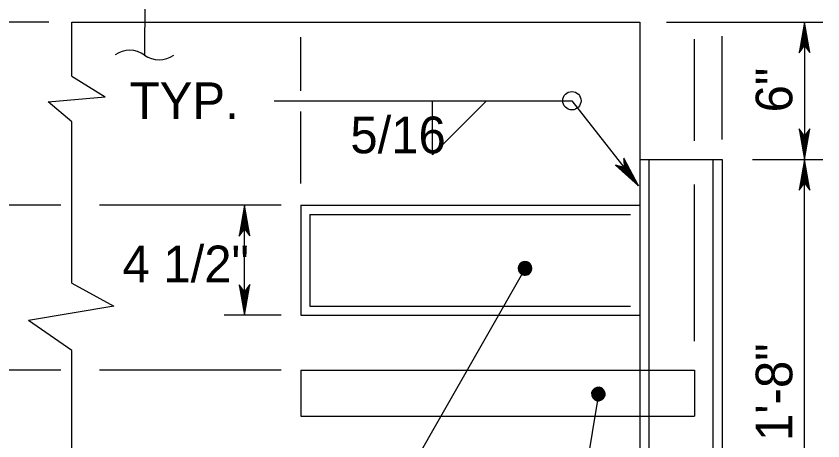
# Model space of a CAD drawing. Extents: x 499866 to 500993, y 499985 to 500645.
# Drawn here: x 500302.2 to 500390.2, y 500532.5 to 500578.8 of the extents above; entities that cross this region are included whole.
import ezdxf

# ---------------------------------------------------------------- set-up
doc = ezdxf.new("R2010")
doc.units = 0
doc.layers.add('24', color=7, linetype='Continuous')
doc.layers.add('5', color=7, linetype='Continuous')

msp = doc.modelspace()

# ---------------------------------------------------------------- linework, layer by layer
at = {"layer": '24'}
for points in [[(500388.193, 500578.176), (500387.6, 500574.826), (500388.193, 500575.626), (500388.776, 500574.843), (500388.193, 500578.176), (500388.198, 500577.953), (500387.644, 500574.92), (500388.2, 500575.689), (500388.73, 500574.978), (500388.209, 500577.833), (500388.193, 500577.722), (500387.731, 500575.123), (500388.199, 500575.706), (500388.654, 500575.107), (500388.192, 500577.671), (500388.209, 500577.559), (500387.799, 500575.288), (500388.192, 500575.73), (500388.601, 500575.279), (500388.21, 500577.236), (500388.209, 500577.047), (500387.884, 500575.456), (500388.183, 500575.766), (500388.516, 500575.432), (500388.193, 500577.013), (500388.182, 500576.834), (500387.977, 500575.638), (500388.21, 500575.868), (500388.439, 500575.619), (500388.193, 500576.67), (500388.176, 500576.501), (500388.038, 500575.783), (500388.2, 500575.901), (500388.379, 500575.706), (500388.192, 500576.414), (500388.081, 500575.945), (500388.209, 500576.013), (500388.338, 500575.807), (500388.21, 500576.296), (500388.133, 500575.989), (500388.234, 500576.117), (500388.294, 500575.969), (500388.2, 500576.116), (500388.183, 500576.04)], [(500388.193, 500563.187), (500388.785, 500566.537), (500388.193, 500565.737), (500387.61, 500566.52), (500388.193, 500563.187), (500388.187, 500563.409), (500388.741, 500566.443), (500388.185, 500565.674), (500387.656, 500566.385), (500388.176, 500563.53), (500388.193, 500563.641), (500388.655, 500566.24), (500388.186, 500565.657), (500387.731, 500566.256), (500388.193, 500563.692), (500388.176, 500563.803), (500388.586, 500566.075), (500388.193, 500565.633), (500387.784, 500566.084), (500388.176, 500564.127), (500388.176, 500564.316), (500388.502, 500565.906), (500388.202, 500565.597), (500387.869, 500565.93), (500388.193, 500564.35), (500388.203, 500564.529), (500388.408, 500565.724), (500388.176, 500565.494), (500387.947, 500565.744), (500388.193, 500564.693), (500388.21, 500564.862), (500388.347, 500565.58), (500388.185, 500565.462), (500388.007, 500565.657), (500388.193, 500564.949), (500388.304, 500565.418), (500388.176, 500565.35), (500388.048, 500565.555), (500388.176, 500565.067), (500388.253, 500565.374), (500388.152, 500565.245), (500388.091, 500565.393), (500388.185, 500565.246), (500388.202, 500565.323)], [(500370.066, 500560.316), (500368.469, 500563.32), (500368.496, 500562.324), (500367.554, 500562.582), (500370.066, 500560.316), (500369.925, 500560.488), (500368.492, 500563.219), (500368.528, 500562.271), (500367.673, 500562.504), (500369.842, 500560.576), (500369.786, 500560.674), (500368.55, 500563.005), (500368.539, 500562.257), (500367.812, 500562.449), (500369.755, 500560.714), (500369.674, 500560.791), (500368.597, 500562.833), (500368.56, 500562.243), (500367.96, 500562.346), (500369.474, 500561.046), (500369.358, 500561.195), (500368.635, 500562.649), (500368.589, 500562.22), (500368.121, 500562.278), (500369.35, 500561.232), (500369.248, 500561.379), (500368.673, 500562.447), (500368.631, 500562.123), (500368.297, 500562.178), (500369.138, 500561.502), (500369.048, 500561.645), (500368.714, 500562.296), (500368.659, 500562.103), (500368.398, 500562.147), (500368.981, 500561.704), (500368.78, 500562.142), (500368.721, 500562.01), (500368.493, 500562.092), (500368.895, 500561.786), (500368.766, 500562.076), (500368.766, 500561.912), (500368.627, 500561.991), (500368.792, 500561.934), (500368.758, 500562.005)], [(500388.193, 500563.187), (500387.6, 500559.837), (500388.193, 500560.637), (500388.776, 500559.854), (500388.193, 500563.187), (500388.198, 500562.965), (500387.644, 500559.931), (500388.2, 500560.7), (500388.73, 500559.99), (500388.209, 500562.844), (500388.193, 500562.733), (500387.731, 500560.134), (500388.199, 500560.717), (500388.654, 500560.118), (500388.192, 500562.682), (500388.209, 500562.571), (500387.799, 500560.299), (500388.192, 500560.741), (500388.601, 500560.29), (500388.21, 500562.247), (500388.209, 500562.058), (500387.884, 500560.468), (500388.183, 500560.777), (500388.516, 500560.444), (500388.193, 500562.024), (500388.182, 500561.845), (500387.977, 500560.65), (500388.21, 500560.88), (500388.439, 500560.63), (500388.193, 500561.681), (500388.176, 500561.512), (500388.038, 500560.794), (500388.2, 500560.912), (500388.379, 500560.717), (500388.192, 500561.425), (500388.081, 500560.956), (500388.209, 500561.024), (500388.338, 500560.819), (500388.21, 500561.307), (500388.133, 500561), (500388.234, 500561.129), (500388.294, 500560.981), (500388.2, 500561.128), (500388.183, 500561.051)], [(500327.091, 500558.191), (500326.499, 500554.841), (500327.091, 500555.641), (500327.674, 500554.858), (500327.091, 500558.191), (500327.097, 500557.969), (500326.543, 500554.935), (500327.098, 500555.704), (500327.628, 500554.993), (500327.108, 500557.848), (500327.091, 500557.737), (500326.629, 500555.138), (500327.098, 500555.721), (500327.553, 500555.122), (500327.091, 500557.686), (500327.108, 500557.574), (500326.698, 500555.303), (500327.091, 500555.745), (500327.5, 500555.294), (500327.108, 500557.251), (500327.108, 500557.062), (500326.782, 500555.471), (500327.082, 500555.781), (500327.415, 500555.448), (500327.091, 500557.028), (500327.081, 500556.849), (500326.876, 500555.654), (500327.108, 500555.884), (500327.337, 500555.634), (500327.091, 500556.685), (500327.074, 500556.516), (500326.937, 500555.798), (500327.098, 500555.916), (500327.277, 500555.721), (500327.091, 500556.429), (500326.98, 500555.96), (500327.108, 500556.028), (500327.236, 500555.823), (500327.108, 500556.311), (500327.031, 500556.004), (500327.132, 500556.133), (500327.193, 500555.985), (500327.098, 500556.132), (500327.082, 500556.055)], [(500357.7, 500551.309), (500315.017, 500476.505), (500305.426, 500476.505)], [(500327.091, 500546.2), (500327.683, 500549.55), (500327.091, 500548.75), (500326.508, 500549.533), (500327.091, 500546.2), (500327.085, 500546.423), (500327.639, 500549.456), (500327.084, 500548.687), (500326.554, 500549.398), (500327.075, 500546.543), (500327.091, 500546.654), (500327.553, 500549.253), (500327.084, 500548.67), (500326.63, 500549.269), (500327.092, 500546.705), (500327.075, 500546.817), (500327.485, 500549.088), (500327.092, 500548.646), (500326.683, 500549.097), (500327.074, 500547.14), (500327.075, 500547.329), (500327.4, 500548.92), (500327.101, 500548.61), (500326.768, 500548.944), (500327.091, 500547.363), (500327.102, 500547.542), (500327.306, 500548.738), (500327.074, 500548.508), (500326.845, 500548.757), (500327.091, 500547.706), (500327.108, 500547.875), (500327.245, 500548.593), (500327.084, 500548.475), (500326.905, 500548.67), (500327.092, 500547.962), (500327.203, 500548.431), (500327.075, 500548.363), (500326.946, 500548.569), (500327.074, 500548.08), (500327.151, 500548.387), (500327.05, 500548.259), (500326.99, 500548.406), (500327.084, 500548.26), (500327.101, 500548.336)], [(500365.696, 500537.609), (500358.156, 500491.828), (500352.28, 500491.828)]]:
    msp.add_lwpolyline(points, dxfattribs=at)
for centre, radius, start, end in [((500314.573, 500572.326), 2.768, 54.46959, 124.83479), ((500317.791, 500576.831), 2.768, 234.46959, 304.83479), ((500357.7, 500551.309), 0.738, 60.29128, 240.29128), ((500357.7, 500551.309), 0.714, 60.29128, 240.29128), ((500357.7, 500551.309), 0.689, 60.29128, 240.29128), ((500357.7, 500551.309), 0.664, 60.29128, 240.29128), ((500357.7, 500551.309), 0.64, 60.29128, 240.29128), ((500357.7, 500551.309), 0.615, 60.29128, 240.29128), ((500357.7, 500551.309), 0.591, 60.29128, 240.29128), ((500357.7, 500551.309), 0.566, 60.29128, 240.29128), ((500357.7, 500551.309), 0.541, 60.29128, 240.29128), ((500357.7, 500551.309), 0.517, 60.29128, 240.29128), ((500357.7, 500551.309), 0.492, 60.29128, 240.29128), ((500357.7, 500551.309), 0.468, 60.29128, 240.29128), ((500357.7, 500551.309), 0.443, 60.29128, 240.29128), ((500357.7, 500551.309), 0.418, 60.29128, 240.29128), ((500357.7, 500551.309), 0.394, 60.29128, 240.29128), ((500357.7, 500551.309), 0.369, 60.29128, 240.29128), ((500357.7, 500551.309), 0.738, 240.29128, 60.29128), ((500357.7, 500551.309), 0.714, 240.29128, 60.29128), ((500357.7, 500551.309), 0.344, 60.29128, 240.29128), ((500357.7, 500551.309), 0.689, 240.29128, 60.29128), ((500357.7, 500551.309), 0.664, 240.29128, 60.29128), ((500357.7, 500551.309), 0.32, 60.29128, 240.29128), ((500357.7, 500551.309), 0.64, 240.29128, 60.29128), ((500357.7, 500551.309), 0.615, 240.29128, 60.29128), ((500357.7, 500551.309), 0.295, 60.29128, 240.29128), ((500357.7, 500551.309), 0.591, 240.29128, 60.29128), ((500357.7, 500551.309), 0.566, 240.29128, 60.29128), ((500357.7, 500551.309), 0.271, 60.29128, 240.29128), ((500357.7, 500551.309), 0.541, 240.29128, 60.29128), ((500357.7, 500551.309), 0.517, 240.29128, 60.29128), ((500357.7, 500551.309), 0.246, 60.29128, 240.29128), ((500357.7, 500551.309), 0.492, 240.29128, 60.29128), ((500357.7, 500551.309), 0.468, 240.29128, 60.29128), ((500357.7, 500551.309), 0.221, 60.29128, 240.29128), ((500357.7, 500551.309), 0.443, 240.29128, 60.29128), ((500357.7, 500551.309), 0.418, 240.29128, 60.29128), ((500357.7, 500551.309), 0.197, 60.29128, 240.29128), ((500357.7, 500551.309), 0.394, 240.29128, 60.29128), ((500357.7, 500551.309), 0.369, 240.29128, 60.29128), ((500357.7, 500551.309), 0.172, 60.29128, 240.29128), ((500357.7, 500551.309), 0.344, 240.29128, 60.29128), ((500357.7, 500551.309), 0.32, 240.29128, 60.29128), ((500357.7, 500551.309), 0.148, 60.29128, 240.29128), ((500357.7, 500551.309), 0.295, 240.29128, 60.29128), ((500357.7, 500551.309), 0.271, 240.29128, 60.29128), ((500357.7, 500551.309), 0.123, 60.29128, 240.29128), ((500357.7, 500551.309), 0.246, 240.29128, 60.29128), ((500357.7, 500551.309), 0.221, 240.29128, 60.29128), ((500357.7, 500551.309), 0.0984, 60.29128, 240.29128), ((500357.7, 500551.309), 0.197, 240.29128, 60.29128), ((500357.7, 500551.309), 0.172, 240.29128, 60.29128), ((500357.7, 500551.309), 0.0738, 60.29128, 240.29128), ((500357.7, 500551.309), 0.148, 240.29128, 60.29128), ((500357.7, 500551.309), 0.123, 240.29128, 60.29128), ((500357.7, 500551.309), 0.0984, 240.29128, 60.29128), ((500357.7, 500551.309), 0.0492, 60.29128, 240.29128), ((500357.7, 500551.309), 0.0738, 240.29128, 60.29128), ((500357.7, 500551.309), 0.0492, 240.29128, 60.29128), ((500357.7, 500551.309), 0.0246, 60.29128, 240.29128), ((500357.7, 500551.309), 0.0246, 240.29128, 60.29128), ((500365.695, 500537.609), 0.738, 80.64766, 260.64766), ((500365.695, 500537.609), 0.714, 80.64766, 260.64766), ((500365.695, 500537.609), 0.689, 80.64766, 260.64766), ((500365.695, 500537.609), 0.664, 80.64766, 260.64766), ((500365.695, 500537.609), 0.64, 80.64766, 260.64766), ((500365.695, 500537.609), 0.615, 80.64766, 260.64766), ((500365.695, 500537.609), 0.591, 80.64766, 260.64766), ((500365.695, 500537.609), 0.566, 80.64766, 260.64766), ((500365.695, 500537.609), 0.541, 80.64766, 260.64766), ((500365.695, 500537.609), 0.517, 80.64766, 260.64766), ((500365.695, 500537.609), 0.492, 80.64766, 260.64766), ((500365.695, 500537.609), 0.468, 80.64766, 260.64766), ((500365.695, 500537.609), 0.443, 80.64766, 260.64766), ((500365.695, 500537.609), 0.418, 80.64766, 260.64766), ((500365.695, 500537.609), 0.394, 80.64766, 260.64766), ((500365.695, 500537.609), 0.369, 80.64766, 260.64766), ((500365.695, 500537.609), 0.344, 80.64766, 260.64766), ((500365.695, 500537.609), 0.32, 80.64766, 260.64766), ((500365.695, 500537.609), 0.295, 80.64766, 260.64766), ((500365.695, 500537.609), 0.271, 80.64766, 260.64766), ((500365.695, 500537.609), 0.738, 260.64766, 80.64766), ((500365.695, 500537.609), 0.714, 260.64766, 80.64766), ((500365.695, 500537.609), 0.689, 260.64766, 80.64766), ((500365.695, 500537.609), 0.664, 260.64766, 80.64766), ((500365.695, 500537.609), 0.64, 260.64766, 80.64766), ((500365.695, 500537.609), 0.615, 260.64766, 80.64766), ((500365.695, 500537.609), 0.591, 260.64766, 80.64766), ((500365.695, 500537.609), 0.566, 260.64766, 80.64766), ((500365.695, 500537.609), 0.541, 260.64766, 80.64766), ((500365.695, 500537.609), 0.517, 260.64766, 80.64766), ((500365.695, 500537.609), 0.492, 260.64766, 80.64766), ((500365.695, 500537.609), 0.468, 260.64766, 80.64766), ((500365.695, 500537.609), 0.443, 260.64766, 80.64766), ((500365.695, 500537.609), 0.418, 260.64766, 80.64766), ((500365.695, 500537.609), 0.394, 260.64766, 80.64766), ((500365.695, 500537.609), 0.369, 260.64766, 80.64766), ((500365.695, 500537.609), 0.344, 260.64766, 80.64766), ((500365.695, 500537.609), 0.32, 260.64766, 80.64766), ((500365.695, 500537.609), 0.295, 260.64766, 80.64766), ((500365.695, 500537.609), 0.271, 260.64766, 80.64766), ((500365.695, 500537.609), 0.246, 80.64766, 260.64766), ((500365.695, 500537.609), 0.221, 80.64766, 260.64766), ((500365.695, 500537.609), 0.197, 80.64766, 260.64766), ((500365.695, 500537.609), 0.172, 80.64766, 260.64766), ((500365.695, 500537.609), 0.148, 80.64766, 260.64766), ((500365.695, 500537.609), 0.123, 80.64766, 260.64766), ((500365.695, 500537.609), 0.0984, 80.64766, 260.64766), ((500365.695, 500537.609), 0.0738, 80.64766, 260.64766), ((500365.695, 500537.609), 0.0492, 80.64766, 260.64766), ((500365.695, 500537.609), 0.246, 260.64766, 80.64766), ((500365.695, 500537.609), 0.221, 260.64766, 80.64766), ((500365.695, 500537.609), 0.197, 260.64766, 80.64766), ((500365.695, 500537.609), 0.172, 260.64766, 80.64766), ((500365.695, 500537.609), 0.148, 260.64766, 80.64766), ((500365.695, 500537.609), 0.0246, 80.64766, 260.64766), ((500365.695, 500537.609), 0.123, 260.64766, 80.64766), ((500365.695, 500537.609), 0.0984, 260.64766, 80.64766), ((500365.695, 500537.609), 0.0738, 260.64766, 80.64766), ((500365.695, 500537.609), 0.0492, 260.64766, 80.64766), ((500365.695, 500537.609), 0.0246, 260.64766, 80.64766)]:
    msp.add_arc(centre, radius, start, end, dxfattribs=at)
at = {"layer": '5'}
for p, q in [((500305.74, 500578.176), (500294.338, 500578.176)), ((500308.254, 500578.176), (500370.206, 500578.176)), ((500308.254, 500572.289), (500308.254, 500578.176)), ((500370.206, 500578.176), (500370.206, 500563.187)), ((500373.132, 500578.176), (500390.192, 500578.176)), ((500388.193, 500578.176), (500388.193, 500563.187)), ((500379.2, 500565.381), (500379.2, 500576.627)), ((500333.235, 500570.667), (500333.235, 500576.538)), ((500376.202, 500565.223), (500376.202, 500576.31)), ((500308.254, 500572.289), (500311.908, 500570.008)), ((500305.687, 500569.478), (500311.908, 500570.008)), ((500330.326, 500569.596), (500362.808, 500569.596)), ((500353.481, 500569.596), (500347.59, 500563.705)), ((500347.59, 500563.705), (500347.59, 500569.596)), ((500362.808, 500569.596), (500370.066, 500560.316)), ((500308.254, 500567.301), (500305.687, 500569.478)), ((500333.235, 500560.554), (500333.235, 500568.406)), ((500308.254, 500549.689), (500308.254, 500567.301)), ((500370.206, 500563.187), (500379.2, 500563.187)), ((500370.206, 500563.187), (500370.206, 500512.226)), ((500371.206, 500563.187), (500371.206, 500512.226)), ((500378.2, 500563.187), (500378.2, 500512.226)), ((500379.2, 500563.187), (500379.2, 500498.237)), ((500382.498, 500563.187), (500390.192, 500563.187)), ((500388.193, 500512.226), (500388.193, 500563.187)), ((500376.202, 500543.365), (500376.202, 500560.471)), ((500307.054, 500558.191), (500294.338, 500558.191)), ((500331.088, 500558.191), (500311.29, 500558.191)), ((500327.091, 500546.2), (500327.091, 500558.191)), ((500333.235, 500558.191), (500370.206, 500558.191)), ((500333.235, 500558.191), (500333.235, 500546.2)), ((500334.234, 500557.192), (500369.207, 500557.192)), ((500334.234, 500557.192), (500334.234, 500547.199)), ((500308.254, 500549.689), (500312.835, 500547.174)), ((500312.835, 500547.174), (500303.525, 500545.63)), ((500334.234, 500547.199), (500369.207, 500547.199)), ((500331.088, 500546.2), (500324.881, 500546.2)), ((500333.235, 500546.2), (500370.206, 500546.2)), ((500308.254, 500542.36), (500303.525, 500545.63)), ((500308.254, 500518.074), (500308.254, 500542.36)), ((500307.054, 500540.205), (500294.338, 500540.205)), ((500331.088, 500540.205), (500311.29, 500540.205)), ((500333.235, 500540.205), (500376.202, 500540.205)), ((500333.235, 500540.205), (500333.235, 500535.208)), ((500376.202, 500540.205), (500376.202, 500535.208)), ((500333.235, 500535.208), (500376.202, 500535.208))]:
    msp.add_line(p, q, dxfattribs=at)
msp.add_lwpolyline([(500306.649, 500592.738), (500316.292, 500592.738), (500316.182, 500574.578)], dxfattribs=at)
msp.add_circle((500362.808, 500569.596), 0.999, dxfattribs=at)

# ---------------------------------------------------------------- texts
for s, p in [('6"', (500386.862, 500568.326)), ('1\'-8"', (500386.862, 500532.479))]:
    msp.add_text(s, height=4, rotation=90, dxfattribs=at).set_placement(p)
for s, p in [('TYP.', (500314.571, 500567.596)), ('5/16', (500338.64, 500563.864)), ('4 1/2"', (500313.784, 500549.796))]:
    msp.add_text(s, height=4, dxfattribs=at).set_placement(p)

doc.saveas('drawing.dxf')
